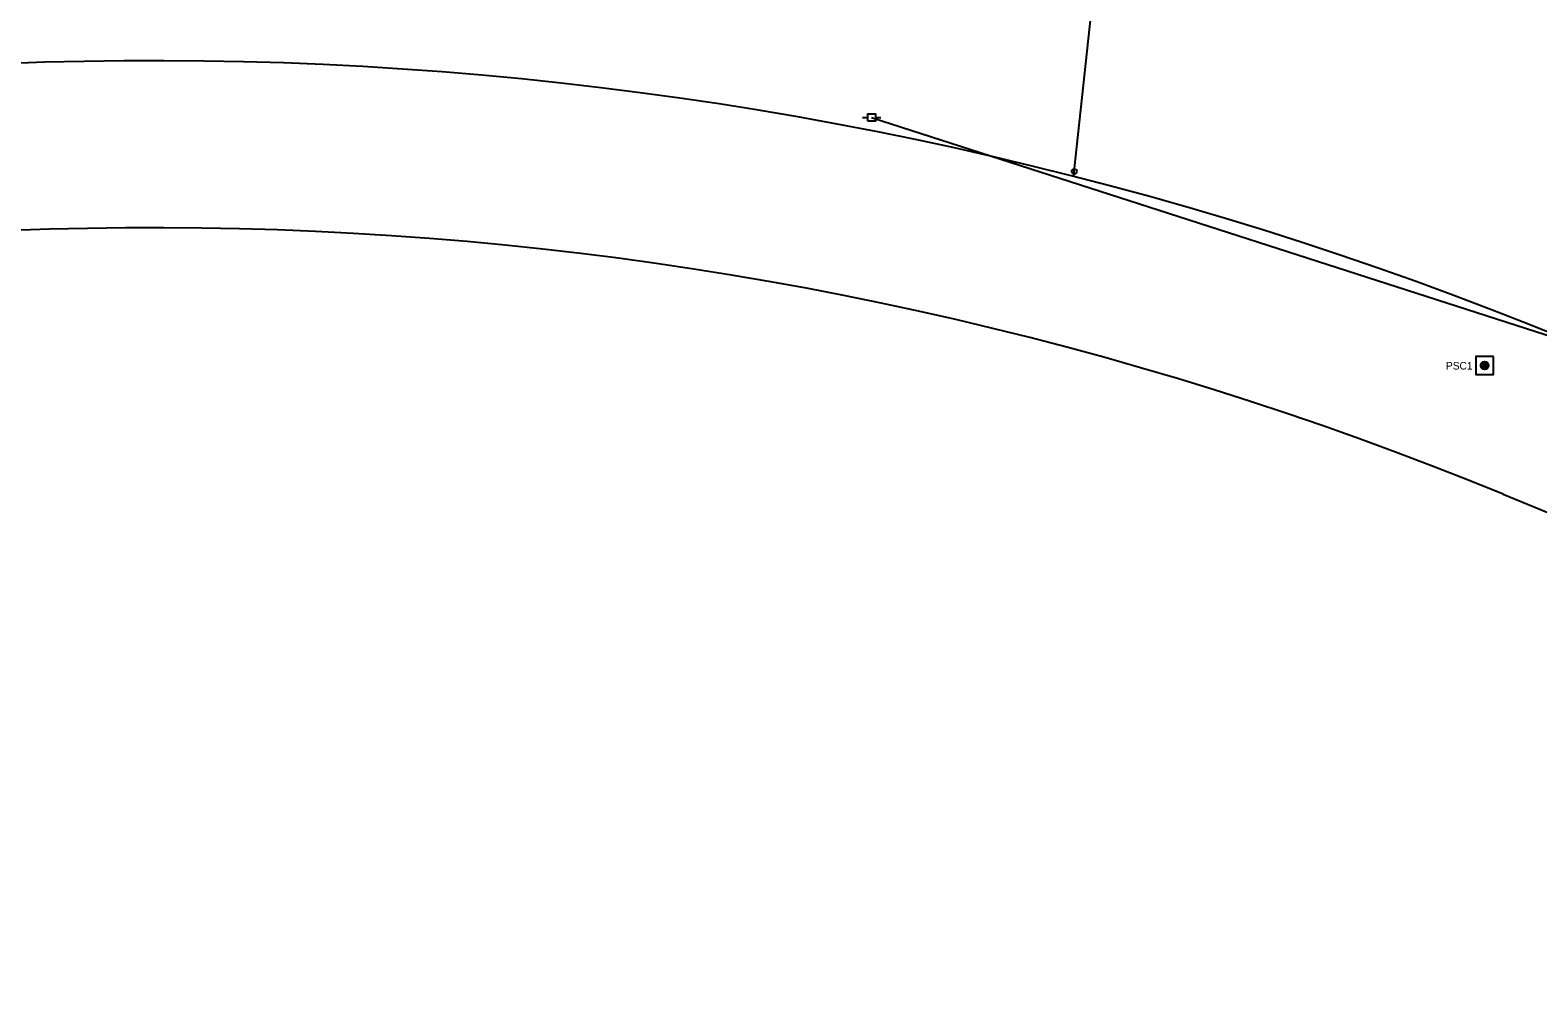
# Model space of a CAD drawing. Extents: x 1903662 to 1907233, y 1108998 to 1112872.
# Drawn here: x 1904257 to 1904853, y 1110132 to 1110517 of the extents above; entities that cross this region are included whole.
import ezdxf

# ---------------------------------------------------------------- set-up
doc = ezdxf.new("R2010")
doc.units = 0
for name, color, linetype in [('RD_EX_DV_Prop', 7, 'Continuous'), ('RD_EX_DV_PropPin', 7, 'Continuous'), ('RD_EX_RW', 7, 'Continuous'), ('RD_EX_UT', 7, 'Continuous'), ('RD_HC_Survey', 7, 'Continuous'), ('RD_HC_Survey_txCode', 7, 'Continuous'), ('SV_UT_Electric_Lines', 7, 'Continuous')]:
    doc.layers.add(name, color=color, linetype=linetype)

msp = doc.modelspace()

# ---------------------------------------------------------------- linework, layer by layer
at = {"layer": 'RD_EX_DV_Prop'}
msp.add_lwpolyline([(1904669.59, 1110459.64), (1904669.8, 1110461.62), (1904813.67, 1111793.47), (1903667.37, 1112032.77), (1903661.66, 1112246.87), (1903737.06, 1112532.52), (1903971.87, 1112635.17), (1904052.3, 1112812.42), (1904167.63, 1112709.72), (1904373.26, 1112872.5), (1904407.95, 1112822.28), (1904436.69, 1112588.3), (1904516.92, 1112466.41), (1904981.8, 1112451.17), (1905086.45, 1112370.71), (1905203.85, 1112404.25), (1906353.04, 1111760.26)], dxfattribs=at)
at = {"layer": 'RD_EX_DV_PropPin'}
msp.add_circle((1904669.8, 1110461.62), 1, dxfattribs=at)
at = {"layer": 'RD_EX_RW'}
msp.add_line((1904839.26, 1110334.07), (1906209.37, 1109772.47), dxfattribs=at)
for radius, start in [(1468.79, 67.6647), (1402.79, 67.66361)]:
    msp.add_arc((1904306.14, 1109036.53), radius, start, 107.11416, dxfattribs=at)
at = {"layer": 'RD_EX_UT'}
for p, q in [((1904586.18, 1110482.84), (1904588.23, 1110482.84)), ((1904589.73, 1110482.88), (1904589.73, 1110482.88)), ((1904591.23, 1110482.84), (1904593.37, 1110482.84))]:
    msp.add_line(p, q, dxfattribs=at)
msp.add_lwpolyline([(1904588.23, 1110481.38), (1904588.23, 1110484.38), (1904591.23, 1110484.38), (1904591.23, 1110481.38)], close=True, dxfattribs=at)
msp.add_lwpolyline([(1904589.73, 1110482.88), (1904891.43, 1110385.65), (1905171.11, 1110270.76), (1905436.6, 1110161.49), (1905735.85, 1110038.44), (1905992.24, 1109932.67), (1906258.29, 1109823.17), (1906443.47, 1109747.31)], dxfattribs=at)
at = {"layer": 'RD_HC_Survey'}
for p, q in [((1904830.41, 1110384.56), (1904830.41, 1110385.29)), ((1904830.46, 1110384.4), (1904830.46, 1110385.45)), ((1904830.51, 1110384.28), (1904830.51, 1110385.58)), ((1904830.56, 1110384.18), (1904830.56, 1110385.68)), ((1904830.61, 1110384.09), (1904830.61, 1110385.76)), ((1904830.66, 1110384.02), (1904830.66, 1110385.83)), ((1904830.71, 1110383.95), (1904830.71, 1110385.9)), ((1904830.76, 1110383.89), (1904830.76, 1110385.96)), ((1904830.81, 1110383.84), (1904830.81, 1110386.01)), ((1904830.86, 1110383.79), (1904830.86, 1110386.06)), ((1904830.91, 1110383.75), (1904830.91, 1110386.11)), ((1904830.96, 1110383.7), (1904830.96, 1110386.15)), ((1904831.01, 1110383.67), (1904831.01, 1110386.19)), ((1904831.06, 1110383.63), (1904831.06, 1110386.22)), ((1904831.11, 1110383.6), (1904831.11, 1110386.25)), ((1904831.16, 1110383.57), (1904831.16, 1110386.28)), ((1904831.21, 1110383.54), (1904831.21, 1110386.31)), ((1904831.26, 1110383.52), (1904831.26, 1110386.33)), ((1904831.31, 1110383.5), (1904831.31, 1110386.36)), ((1904831.36, 1110383.48), (1904831.36, 1110386.38)), ((1904831.41, 1110383.46), (1904831.41, 1110386.39)), ((1904831.46, 1110383.44), (1904831.46, 1110386.41)), ((1904831.51, 1110383.43), (1904831.51, 1110386.43)), ((1904831.56, 1110383.41), (1904831.56, 1110386.44)), ((1904831.61, 1110383.4), (1904831.61, 1110386.45)), ((1904831.66, 1110383.39), (1904831.66, 1110386.46)), ((1904831.71, 1110383.39), (1904831.71, 1110386.47)), ((1904831.76, 1110383.38), (1904831.76, 1110386.47)), ((1904831.81, 1110383.38), (1904831.81, 1110386.48)), ((1904831.86, 1110383.37), (1904831.86, 1110386.48)), ((1904831.91, 1110383.37), (1904831.91, 1110386.48)), ((1904831.96, 1110383.37), (1904831.96, 1110386.48)), ((1904832.01, 1110383.37), (1904832.01, 1110386.48)), ((1904832.06, 1110383.38), (1904832.06, 1110386.47)), ((1904832.11, 1110383.38), (1904832.11, 1110386.47)), ((1904832.16, 1110383.39), (1904832.16, 1110386.46)), ((1904832.21, 1110383.4), (1904832.21, 1110386.45)), ((1904832.26, 1110383.41), (1904832.26, 1110386.44)), ((1904832.31, 1110383.42), (1904832.31, 1110386.43)), ((1904832.36, 1110383.43), (1904832.36, 1110386.42)), ((1904832.41, 1110383.45), (1904832.41, 1110386.4)), ((1904832.46, 1110383.47), (1904832.46, 1110386.38)), ((1904832.51, 1110383.49), (1904832.51, 1110386.37)), ((1904832.56, 1110383.51), (1904832.56, 1110386.34)), ((1904832.61, 1110383.53), (1904832.61, 1110386.32)), ((1904832.66, 1110383.56), (1904832.66, 1110386.29)), ((1904832.71, 1110383.59), (1904832.71, 1110386.27)), ((1904832.76, 1110383.62), (1904832.76, 1110386.24)), ((1904832.81, 1110383.65), (1904832.81, 1110386.2)), ((1904832.86, 1110383.69), (1904832.86, 1110386.17)), ((1904832.91, 1110383.73), (1904832.91, 1110386.13)), ((1904832.96, 1110383.77), (1904832.96, 1110386.08)), ((1904833.01, 1110383.82), (1904833.01, 1110386.04)), ((1904833.06, 1110383.87), (1904833.06, 1110385.98)), ((1904833.11, 1110383.92), (1904833.11, 1110385.93)), ((1904833.16, 1110383.99), (1904833.16, 1110385.87)), ((1904833.21, 1110384.06), (1904833.21, 1110385.8)), ((1904833.26, 1110384.13), (1904833.26, 1110385.72)), ((1904833.31, 1110384.23), (1904833.31, 1110385.63)), ((1904833.36, 1110384.34), (1904833.36, 1110385.52)), ((1904833.41, 1110384.48), (1904833.41, 1110385.38)), ((1904833.46, 1110384.7), (1904833.46, 1110385.15))]:
    msp.add_line(p, q, dxfattribs=at)
msp.add_lwpolyline([(1904835.46, 1110388.46), (1904828.39, 1110388.46), (1904828.39, 1110381.39), (1904835.46, 1110381.39)], close=True, dxfattribs=at)
msp.add_circle((1904831.93, 1110384.93), 1.55, dxfattribs=at)
at = {"layer": 'SV_UT_Electric_Lines'}
msp.add_lwpolyline([(1904589.73, 1110482.88), (1904891.43, 1110385.65), (1905171.11, 1110270.76), (1905436.6, 1110161.49), (1905735.85, 1110038.44), (1905992.24, 1109932.67), (1906258.29, 1109823.17), (1906443.47, 1109747.31)], dxfattribs=at)

# ---------------------------------------------------------------- texts
at = {"layer": 'RD_HC_Survey_txCode'}
msp.add_text('PSC1', height=3, dxfattribs=at).set_placement((1904816.65, 1110383.32))

doc.saveas('drawing.dxf')
